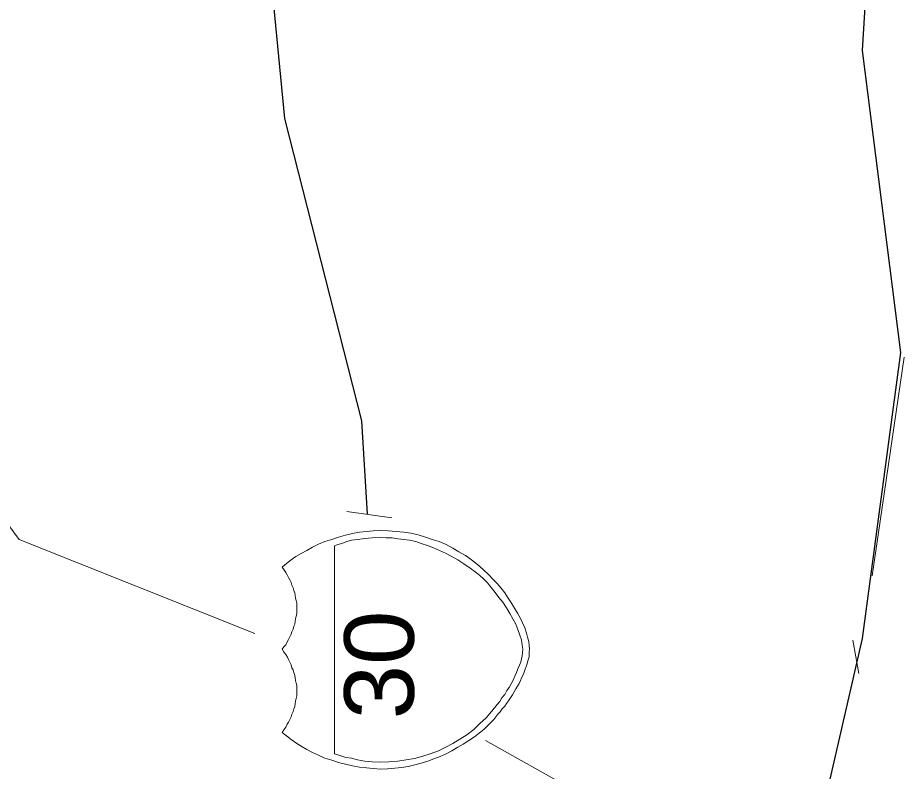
# Model space of a CAD drawing. Extents: x 2363323 to 2367082, y 6956018 to 6980837.
# Drawn here: x 2366007.5 to 2366072.4, y 6956774.4 to 6956829.6 of the extents above; entities that cross this region are included whole.
import ezdxf

# ---------------------------------------------------------------- set-up
doc = ezdxf.new("R2010")
doc.units = 0
doc.header["$LTSCALE"] = 4.1
doc.layers.add('62', color=7, linetype='Continuous', lineweight=13)
doc.layers.add('63', color=7, linetype='Continuous', lineweight=13)

msp = doc.modelspace()

# ---------------------------------------------------------------- linework, layer by layer
at = {"layer": '62'}
for p, q in [((2366072.428, 6956804.76), (2366070.064, 6956788.74)), ((2366031.587, 6956793.462), (2366034.871, 6956792.991)), ((2366069.097, 6956781.584), (2366068.647, 6956784.038)), ((2366041.733, 6956776.678), (2366062.997, 6956764.818))]:
    msp.add_line(p, q, dxfattribs=at)
at = {"layer": '62', "lineweight": 25}
for points in [[(2366063.045, 6956932.21), (2366064.574, 6956924.38), (2366065.453, 6956914.39), (2366066.511, 6956900.348), (2366066.509, 6956890.358), (2366067.387, 6956883.202), (2366070.199, 6956878.208), (2366072.157, 6956868.194), (2366071.099, 6956854.152), (2366070.199, 6956841.303), (2366069.344, 6956827.239), (2366072.158, 6956805.098), (2366069.344, 6956784.148), (2366065.451, 6956767.248), (2366059.984, 6956757.237), (2366046.773, 6956754.154), (2366033.545, 6956754.153), (2366027.019, 6956752.263), (2366017.681, 6956757.237)], [(2366020.359, 6956868.105), (2366024.206, 6956851.294), (2366027.02, 6956822.244), (2366032.667, 6956800.101), (2366033.073, 6956793.261)]]:
    msp.add_lwpolyline(points, dxfattribs=at)
at = {"layer": '62'}
for points in [[(2365993.333, 6956810.632), (2366007.575, 6956791.416), (2366024.836, 6956784.508)], [(2366027.313, 6956784.081), (2366027.403, 6956784.284), (2366027.491, 6956784.464), (2366027.56, 6956784.644), (2366027.65, 6956784.846), (2366027.695, 6956785.05), (2366027.761, 6956785.208), (2366027.806, 6956785.408), (2366027.83, 6956785.588), (2366027.875, 6956785.79), (2366027.919, 6956785.972), (2366027.92, 6956786.174), (2366027.92, 6956786.376), (2366027.92, 6956786.556), (2366027.919, 6956786.734), (2366027.873, 6956786.938), (2366027.83, 6956787.118), (2366027.806, 6956787.298), (2366027.761, 6956787.502), (2366027.693, 6956787.681), (2366027.649, 6956787.861), (2366027.56, 6956788.064), (2366027.491, 6956788.266), (2366027.401, 6956788.446), (2366027.311, 6956788.628), (2366027.219, 6956788.806), (2366027.109, 6956788.986), (2366026.973, 6956789.211), (2366026.839, 6956789.391), (2366027.153, 6956789.638), (2366027.493, 6956789.91), (2366027.851, 6956790.156), (2366028.235, 6956790.381), (2366028.639, 6956790.606), (2366029.066, 6956790.855), (2366029.517, 6956791.056), (2366029.966, 6956791.26), (2366030.485, 6956791.418), (2366030.979, 6956791.574), (2366031.473, 6956791.731), (2366031.991, 6956791.845), (2366032.509, 6956791.934), (2366033.026, 6956792.001), (2366033.521, 6956792.046), (2366034.061, 6956792.068), (2366034.603, 6956792.046), (2366035.187, 6956792.001), (2366035.749, 6956791.934), (2366036.266, 6956791.866), (2366036.806, 6956791.755), (2366037.346, 6956791.574), (2366037.843, 6956791.416), (2366038.359, 6956791.26), (2366038.855, 6956791.035), (2366039.349, 6956790.764), (2366039.8, 6956790.514), (2366040.273, 6956790.225), (2366040.721, 6956789.908), (2366041.149, 6956789.571), (2366041.576, 6956789.211), (2366041.983, 6956788.806), (2366042.275, 6956788.491), (2366042.59, 6956788.176), (2366042.883, 6956787.837), (2366043.153, 6956787.5), (2366043.4, 6956787.118), (2366043.646, 6956786.736), (2366043.871, 6956786.376), (2366044.096, 6956786.016), (2366044.276, 6956785.656), (2366044.456, 6956785.296), (2366044.613, 6956784.936), (2366044.75, 6956784.554), (2366044.817, 6956784.26), (2366044.906, 6956783.924), (2366044.951, 6956783.632), (2366044.973, 6956783.361)], [(2366044.973, 6956783.361), (2366044.953, 6956783.181), (2366044.951, 6956783.025), (2366044.93, 6956782.821), (2366044.883, 6956782.664), (2366044.839, 6956782.506), (2366044.793, 6956782.305), (2366044.727, 6956782.101), (2366044.659, 6956781.898), (2366044.569, 6956781.696), (2366044.503, 6956781.495), (2366044.389, 6956781.268), (2366044.299, 6956781.088), (2366044.21, 6956780.865), (2366044.096, 6956780.661), (2366043.961, 6956780.458), (2366043.849, 6956780.235), (2366043.715, 6956780.03), (2366043.579, 6956779.806), (2366043.421, 6956779.581), (2366043.286, 6956779.402), (2366043.151, 6956779.2), (2366042.971, 6956778.994), (2366042.815, 6956778.77), (2366042.656, 6956778.614), (2366042.499, 6956778.411), (2366042.341, 6956778.231), (2366042.163, 6956778.03), (2366042.003, 6956777.872), (2366041.823, 6956777.692), (2366041.666, 6956777.534), (2366041.487, 6956777.398), (2366041.306, 6956777.241), (2366040.925, 6956776.948), (2366040.52, 6956776.678), (2366040.113, 6956776.407), (2366039.71, 6956776.18), (2366039.281, 6956775.933), (2366038.855, 6956775.71), (2366038.426, 6956775.506), (2366037.953, 6956775.327), (2366037.526, 6956775.171), (2366037.029, 6956775.012), (2366036.559, 6956774.901), (2366036.087, 6956774.787), (2366035.589, 6956774.697), (2366035.096, 6956774.652), (2366034.556, 6956774.607), (2366034.063, 6956774.583), (2366033.521, 6956774.63), (2366033.026, 6956774.674), (2366032.51, 6956774.72), (2366031.991, 6956774.83), (2366031.473, 6956774.946), (2366030.979, 6956775.08), (2366030.483, 6956775.237), (2366029.967, 6956775.393), (2366029.516, 6956775.598), (2366029.066, 6956775.8), (2366028.639, 6956776.024), (2366028.235, 6956776.272), (2366027.851, 6956776.521), (2366027.491, 6956776.748), (2366027.153, 6956777.016), (2366026.84, 6956777.264), (2366026.975, 6956777.466), (2366027.11, 6956777.668), (2366027.221, 6956777.871), (2366027.313, 6956778.028), (2366027.403, 6956778.23), (2366027.491, 6956778.411), (2366027.559, 6956778.615), (2366027.647, 6956778.816), (2366027.693, 6956778.996), (2366027.763, 6956779.176), (2366027.806, 6956779.378), (2366027.829, 6956779.558), (2366027.873, 6956779.761), (2366027.919, 6956779.942), (2366027.919, 6956780.121), (2366027.919, 6956780.348), (2366027.919, 6956780.505), (2366027.919, 6956780.704), (2366027.873, 6956780.888), (2366027.829, 6956781.088), (2366027.807, 6956781.268), (2366027.763, 6956781.448), (2366027.693, 6956781.651), (2366027.649, 6956781.854), (2366027.559, 6956782.012), (2366027.493, 6956782.214), (2366027.401, 6956782.416), (2366027.311, 6956782.618), (2366027.223, 6956782.778), (2366027.107, 6956782.978), (2366026.973, 6956783.158), (2366026.84, 6956783.362), (2366026.973, 6956783.541), (2366027.109, 6956783.7), (2366027.221, 6956783.901), (2366027.313, 6956784.081)]]:
    msp.add_lwpolyline(points, dxfattribs=at)
msp.add_lwpolyline([(2366030.686, 6956790.942), (2366030.686, 6956775.71), (2366030.913, 6956775.642), (2366031.203, 6956775.53), (2366031.519, 6956775.44), (2366031.923, 6956775.374), (2366032.373, 6956775.26), (2366032.891, 6956775.17), (2366033.433, 6956775.124), (2366034.061, 6956775.1), (2366034.67, 6956775.124), (2366035.321, 6956775.17), (2366035.93, 6956775.26), (2366036.536, 6956775.372), (2366037.143, 6956775.53), (2366037.683, 6956775.71), (2366038.291, 6956775.934), (2366038.833, 6956776.182), (2366039.349, 6956776.452), (2366039.867, 6956776.768), (2366040.383, 6956777.106), (2366040.88, 6956777.488), (2366041.33, 6956777.916), (2366041.779, 6956778.345), (2366042.183, 6956778.816), (2366042.59, 6956779.311), (2366042.791, 6956779.536), (2366042.949, 6956779.806), (2366043.153, 6956780.054), (2366043.31, 6956780.346), (2366043.466, 6956780.571), (2366043.625, 6956780.841), (2366043.759, 6956781.111), (2366043.893, 6956781.404), (2366044.007, 6956781.651), (2366044.119, 6956781.922), (2366044.231, 6956782.191), (2366044.321, 6956782.418), (2366044.389, 6956782.665), (2366044.433, 6956782.888), (2366044.456, 6956783.136), (2366044.479, 6956783.361), (2366044.433, 6956783.674), (2366044.39, 6956784.058), (2366044.253, 6956784.396), (2366044.12, 6956784.824), (2366043.961, 6956785.206), (2366043.736, 6956785.59), (2366043.533, 6956785.994), (2366043.286, 6956786.398), (2366043.016, 6956786.805), (2366042.725, 6956787.162), (2366042.455, 6956787.524), (2366042.161, 6956787.884), (2366041.891, 6956788.221), (2366041.623, 6956788.491), (2366041.33, 6956788.761), (2366041.081, 6956788.964), (2366040.61, 6956789.302), (2366040.159, 6956789.616), (2366039.709, 6956789.91), (2366039.237, 6956790.178), (2366038.809, 6956790.404), (2366038.36, 6956790.608), (2366037.931, 6956790.808), (2366037.483, 6956790.966), (2366037.033, 6956791.124), (2366036.626, 6956791.258), (2366036.176, 6956791.348), (2366035.749, 6956791.418), (2366035.321, 6956791.461), (2366034.893, 6956791.53), (2366034.466, 6956791.528), (2366034.063, 6956791.552), (2366033.433, 6956791.53), (2366032.893, 6956791.484), (2366032.373, 6956791.416), (2366031.925, 6956791.348), (2366031.519, 6956791.236), (2366031.205, 6956791.124), (2366030.911, 6956791.035)], close=True, dxfattribs=at)
at = {"layer": '63'}
for p, q in [((2366072.428, 6956804.76), (2366070.064, 6956788.74)), ((2366031.587, 6956793.462), (2366034.871, 6956792.991)), ((2366069.097, 6956781.584), (2366068.647, 6956784.038)), ((2366041.733, 6956776.678), (2366062.997, 6956764.818))]:
    msp.add_line(p, q, dxfattribs=at)
at = {"layer": '63', "lineweight": 25}
for points in [[(2366063.045, 6956932.21), (2366064.574, 6956924.38), (2366065.453, 6956914.39), (2366066.511, 6956900.348), (2366066.509, 6956890.358), (2366067.387, 6956883.202), (2366070.199, 6956878.208), (2366072.157, 6956868.194), (2366071.099, 6956854.152), (2366070.199, 6956841.303), (2366069.344, 6956827.239), (2366072.158, 6956805.098), (2366069.344, 6956784.148), (2366065.451, 6956767.248), (2366059.984, 6956757.237), (2366046.773, 6956754.154), (2366033.545, 6956754.153), (2366027.019, 6956752.263), (2366017.681, 6956757.237)], [(2366020.359, 6956868.105), (2366024.206, 6956851.294), (2366027.02, 6956822.244), (2366032.667, 6956800.101), (2366033.073, 6956793.261)]]:
    msp.add_lwpolyline(points, dxfattribs=at)
at = {"layer": '63'}
for points in [[(2365993.333, 6956810.632), (2366007.575, 6956791.416), (2366024.836, 6956784.508)], [(2366027.313, 6956784.081), (2366027.403, 6956784.284), (2366027.491, 6956784.464), (2366027.56, 6956784.644), (2366027.65, 6956784.846), (2366027.695, 6956785.05), (2366027.761, 6956785.208), (2366027.806, 6956785.408), (2366027.83, 6956785.588), (2366027.875, 6956785.79), (2366027.919, 6956785.972), (2366027.92, 6956786.174), (2366027.92, 6956786.376), (2366027.92, 6956786.556), (2366027.919, 6956786.734), (2366027.873, 6956786.938), (2366027.83, 6956787.118), (2366027.806, 6956787.298), (2366027.761, 6956787.502), (2366027.693, 6956787.681), (2366027.649, 6956787.861), (2366027.56, 6956788.064), (2366027.491, 6956788.266), (2366027.401, 6956788.446), (2366027.311, 6956788.628), (2366027.219, 6956788.806), (2366027.109, 6956788.986), (2366026.973, 6956789.211), (2366026.839, 6956789.391), (2366027.153, 6956789.638), (2366027.493, 6956789.91), (2366027.851, 6956790.156), (2366028.235, 6956790.381), (2366028.639, 6956790.606), (2366029.066, 6956790.855), (2366029.517, 6956791.056), (2366029.966, 6956791.26), (2366030.485, 6956791.418), (2366030.979, 6956791.574), (2366031.473, 6956791.731), (2366031.991, 6956791.845), (2366032.509, 6956791.934), (2366033.026, 6956792.001), (2366033.521, 6956792.046), (2366034.061, 6956792.068), (2366034.603, 6956792.046), (2366035.187, 6956792.001), (2366035.749, 6956791.934), (2366036.266, 6956791.866), (2366036.806, 6956791.755), (2366037.346, 6956791.574), (2366037.843, 6956791.416), (2366038.359, 6956791.26), (2366038.855, 6956791.035), (2366039.349, 6956790.764), (2366039.8, 6956790.514), (2366040.273, 6956790.225), (2366040.721, 6956789.908), (2366041.149, 6956789.571), (2366041.576, 6956789.211), (2366041.983, 6956788.806), (2366042.275, 6956788.491), (2366042.59, 6956788.176), (2366042.883, 6956787.837), (2366043.153, 6956787.5), (2366043.4, 6956787.118), (2366043.646, 6956786.736), (2366043.871, 6956786.376), (2366044.096, 6956786.016), (2366044.276, 6956785.656), (2366044.456, 6956785.296), (2366044.613, 6956784.936), (2366044.75, 6956784.554), (2366044.817, 6956784.26), (2366044.906, 6956783.924), (2366044.951, 6956783.632), (2366044.973, 6956783.361)], [(2366044.973, 6956783.361), (2366044.953, 6956783.181), (2366044.951, 6956783.025), (2366044.93, 6956782.821), (2366044.883, 6956782.664), (2366044.839, 6956782.506), (2366044.793, 6956782.305), (2366044.727, 6956782.101), (2366044.659, 6956781.898), (2366044.569, 6956781.696), (2366044.503, 6956781.495), (2366044.389, 6956781.268), (2366044.299, 6956781.088), (2366044.21, 6956780.865), (2366044.096, 6956780.661), (2366043.961, 6956780.458), (2366043.849, 6956780.235), (2366043.715, 6956780.03), (2366043.579, 6956779.806), (2366043.421, 6956779.581), (2366043.286, 6956779.402), (2366043.151, 6956779.2), (2366042.971, 6956778.994), (2366042.815, 6956778.77), (2366042.656, 6956778.614), (2366042.499, 6956778.411), (2366042.341, 6956778.231), (2366042.163, 6956778.03), (2366042.003, 6956777.872), (2366041.823, 6956777.692), (2366041.666, 6956777.534), (2366041.487, 6956777.398), (2366041.306, 6956777.241), (2366040.925, 6956776.948), (2366040.52, 6956776.678), (2366040.113, 6956776.407), (2366039.71, 6956776.18), (2366039.281, 6956775.933), (2366038.855, 6956775.71), (2366038.426, 6956775.506), (2366037.953, 6956775.327), (2366037.526, 6956775.171), (2366037.029, 6956775.012), (2366036.559, 6956774.901), (2366036.087, 6956774.787), (2366035.589, 6956774.697), (2366035.096, 6956774.652), (2366034.556, 6956774.607), (2366034.063, 6956774.583), (2366033.521, 6956774.63), (2366033.026, 6956774.674), (2366032.51, 6956774.72), (2366031.991, 6956774.83), (2366031.473, 6956774.946), (2366030.979, 6956775.08), (2366030.483, 6956775.237), (2366029.967, 6956775.393), (2366029.516, 6956775.598), (2366029.066, 6956775.8), (2366028.639, 6956776.024), (2366028.235, 6956776.272), (2366027.851, 6956776.521), (2366027.491, 6956776.748), (2366027.153, 6956777.016), (2366026.84, 6956777.264), (2366026.975, 6956777.466), (2366027.11, 6956777.668), (2366027.221, 6956777.871), (2366027.313, 6956778.028), (2366027.403, 6956778.23), (2366027.491, 6956778.411), (2366027.559, 6956778.615), (2366027.647, 6956778.816), (2366027.693, 6956778.996), (2366027.763, 6956779.176), (2366027.806, 6956779.378), (2366027.829, 6956779.558), (2366027.873, 6956779.761), (2366027.919, 6956779.942), (2366027.919, 6956780.121), (2366027.919, 6956780.348), (2366027.919, 6956780.505), (2366027.919, 6956780.704), (2366027.873, 6956780.888), (2366027.829, 6956781.088), (2366027.807, 6956781.268), (2366027.763, 6956781.448), (2366027.693, 6956781.651), (2366027.649, 6956781.854), (2366027.559, 6956782.012), (2366027.493, 6956782.214), (2366027.401, 6956782.416), (2366027.311, 6956782.618), (2366027.223, 6956782.778), (2366027.107, 6956782.978), (2366026.973, 6956783.158), (2366026.84, 6956783.362), (2366026.973, 6956783.541), (2366027.109, 6956783.7), (2366027.221, 6956783.901), (2366027.313, 6956784.081)]]:
    msp.add_lwpolyline(points, dxfattribs=at)
msp.add_lwpolyline([(2366030.686, 6956790.942), (2366030.686, 6956775.71), (2366030.913, 6956775.642), (2366031.203, 6956775.53), (2366031.519, 6956775.44), (2366031.923, 6956775.374), (2366032.373, 6956775.26), (2366032.891, 6956775.17), (2366033.433, 6956775.124), (2366034.061, 6956775.1), (2366034.67, 6956775.124), (2366035.321, 6956775.17), (2366035.93, 6956775.26), (2366036.536, 6956775.372), (2366037.143, 6956775.53), (2366037.683, 6956775.71), (2366038.291, 6956775.934), (2366038.833, 6956776.182), (2366039.349, 6956776.452), (2366039.867, 6956776.768), (2366040.383, 6956777.106), (2366040.88, 6956777.488), (2366041.33, 6956777.916), (2366041.779, 6956778.345), (2366042.183, 6956778.816), (2366042.59, 6956779.311), (2366042.791, 6956779.536), (2366042.949, 6956779.806), (2366043.153, 6956780.054), (2366043.31, 6956780.346), (2366043.466, 6956780.571), (2366043.625, 6956780.841), (2366043.759, 6956781.111), (2366043.893, 6956781.404), (2366044.007, 6956781.651), (2366044.119, 6956781.922), (2366044.231, 6956782.191), (2366044.321, 6956782.418), (2366044.389, 6956782.665), (2366044.433, 6956782.888), (2366044.456, 6956783.136), (2366044.479, 6956783.361), (2366044.433, 6956783.674), (2366044.39, 6956784.058), (2366044.253, 6956784.396), (2366044.12, 6956784.824), (2366043.961, 6956785.206), (2366043.736, 6956785.59), (2366043.533, 6956785.994), (2366043.286, 6956786.398), (2366043.016, 6956786.805), (2366042.725, 6956787.162), (2366042.455, 6956787.524), (2366042.161, 6956787.884), (2366041.891, 6956788.221), (2366041.623, 6956788.491), (2366041.33, 6956788.761), (2366041.081, 6956788.964), (2366040.61, 6956789.302), (2366040.159, 6956789.616), (2366039.709, 6956789.91), (2366039.237, 6956790.178), (2366038.809, 6956790.404), (2366038.36, 6956790.608), (2366037.931, 6956790.808), (2366037.483, 6956790.966), (2366037.033, 6956791.124), (2366036.626, 6956791.258), (2366036.176, 6956791.348), (2366035.749, 6956791.418), (2366035.321, 6956791.461), (2366034.893, 6956791.53), (2366034.466, 6956791.528), (2366034.063, 6956791.552), (2366033.433, 6956791.53), (2366032.893, 6956791.484), (2366032.373, 6956791.416), (2366031.925, 6956791.348), (2366031.519, 6956791.236), (2366031.205, 6956791.124), (2366030.911, 6956791.035)], close=True, dxfattribs=at)

# ---------------------------------------------------------------- texts
at = {"layer": '62', "width": 1.05}
msp.add_text('30', height=5.099, rotation=90, dxfattribs=at).set_placement((2366036.49, 6956778.233))
at = {"layer": '63', "width": 1.05}
msp.add_text('30', height=5.099, rotation=90, dxfattribs=at).set_placement((2366036.49, 6956778.233))

doc.saveas('drawing.dxf')
